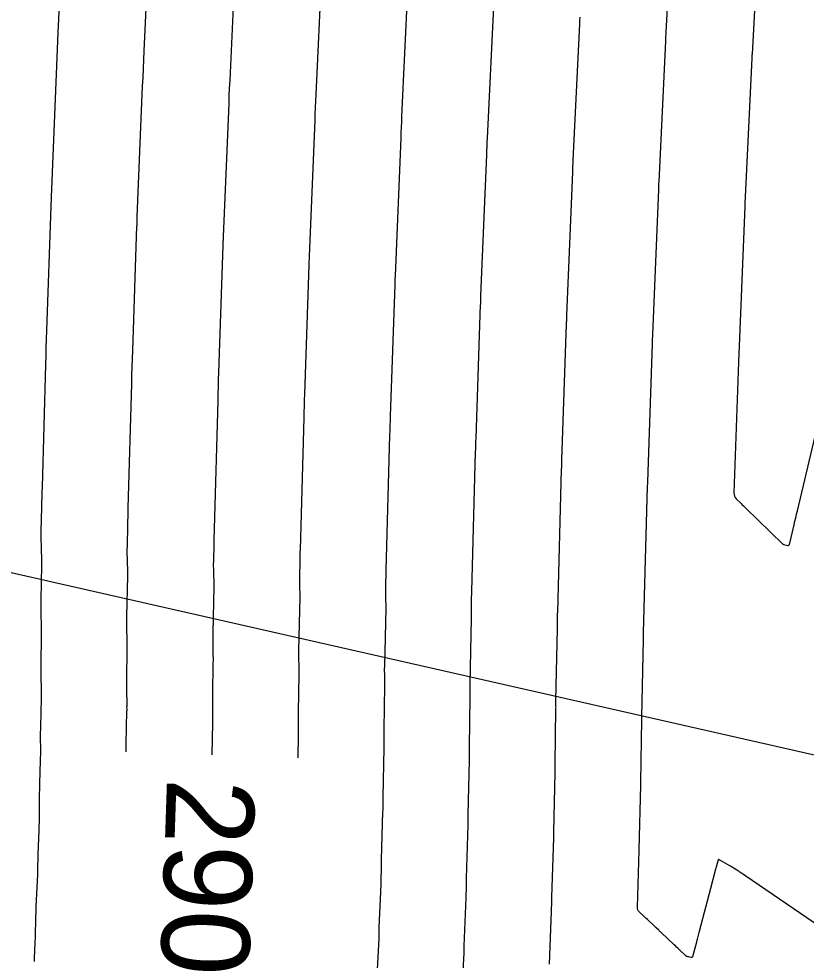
# Model space of a CAD drawing. Extents: x 1710723 to 1713003, y 548603 to 551142.
# Drawn here: x 1712182.6 to 1712236.2, y 549615.6 to 549679.7 of the extents above; entities that cross this region are included whole.
import ezdxf

# ---------------------------------------------------------------- set-up
doc = ezdxf.new("R2010")
doc.units = 0
for name, color, linetype in [('R_Contour Annot', 7, 'Continuous'), ('R_Contours', 7, 'Continuous'), ('R_Horz Alg', 7, 'Continuous'), ('R_Horz Alg Annot', 7, 'Continuous')]:
    doc.layers.add(name, color=color, linetype=linetype)

msp = doc.modelspace()

# ---------------------------------------------------------------- linework, layer by layer
at = {"layer": 'R_Contours'}
for points in [[(1712237.192, 549617.833), (1712232.116, 549621.311), (1712232.014, 549621.381), (1712231.912, 549621.451), (1712231.707, 549621.591), (1712231.656, 549621.626), (1712231.604, 549621.661), (1712231.552, 549621.694), (1712231.5, 549621.728), (1712231.251, 549621.885), (1712231.192, 549621.922), (1712231.132, 549621.959), (1712231.072, 549621.994), (1712231.012, 549622.028), (1712230.377, 549622.385), (1712230.347, 549622.402), (1712230.317, 549622.419), (1712230.257, 549622.452), (1712230.244, 549622.457), (1712230.233, 549622.456), (1712230.224, 549622.449), (1712230.219, 549622.435), (1712230.088, 549621.918), (1712230.08, 549621.888), (1712230.072, 549621.858), (1712230.065, 549621.828), (1712230.057, 549621.798), (1712229.706, 549620.462), (1712228.94, 549617.547), (1712228.93, 549617.511), (1712228.92, 549617.475), (1712228.798, 549617.017), (1712228.784, 549616.965), (1712228.77, 549616.913), (1712228.756, 549616.861), (1712228.742, 549616.809), (1712228.473, 549615.825), (1712228.46, 549615.796), (1712228.441, 549615.777), (1712228.416, 549615.77), (1712228.384, 549615.773), (1712228.207, 549615.819), (1712228.175, 549615.827), (1712228.144, 549615.835), (1712228.082, 549615.851), (1712228.067, 549615.856), (1712228.053, 549615.863), (1712228.04, 549615.872), (1712228.027, 549615.882), (1712227.562, 549616.327), (1712227.481, 549616.405), (1712227.399, 549616.483), (1712227.317, 549616.56), (1712227.235, 549616.638), (1712226.343, 549617.477), (1712226.301, 549617.516), (1712226.259, 549617.555), (1712226.217, 549617.595), (1712226.176, 549617.634), (1712226.009, 549617.792), (1712225.967, 549617.831), (1712225.926, 549617.87), (1712225.884, 549617.909), (1712225.842, 549617.949), (1712225.48, 549618.288), (1712225.406, 549618.357), (1712225.331, 549618.427), (1712225.257, 549618.496), (1712225.183, 549618.566), (1712224.877, 549618.852), (1712224.811, 549618.926), (1712224.765, 549619.01), (1712224.739, 549619.101), (1712224.732, 549619.2), (1712224.851, 549623.058), (1712224.851, 549623.074), (1712224.851, 549623.097), (1712224.851, 549623.105), (1712224.951, 549627.52), (1712224.951, 549627.536), (1712224.953, 549627.622), (1712224.953, 549627.641), (1712224.953, 549627.66), (1712224.953, 549627.699), (1712224.953, 549627.718), (1712224.953, 549627.738), (1712225.023, 549631.965), (1712225.023, 549631.979), (1712225.023, 549631.993), (1712225.023, 549632.008), (1712225.023, 549632.022), (1712225.022, 549632.079), (1712225.022, 549632.094), (1712225.021, 549632.108), (1712225.022, 549632.122), (1712225.022, 549632.136), (1712225.144, 549637.427), (1712225.144, 549637.433), (1712225.141, 549637.548), (1712225.14, 549637.567), (1712225.14, 549637.586), (1712225.14, 549637.605), (1712225.14, 549637.625), (1712225.144, 549637.764), (1712225.144, 549637.793), (1712225.145, 549637.823), (1712225.146, 549637.852), (1712225.147, 549637.882), (1712225.423, 549647.854), (1712225.425, 549647.933), (1712225.428, 549648.013), (1712225.43, 549648.093), (1712225.433, 549648.173), (1712225.754, 549657.576), (1712225.756, 549657.633), (1712225.758, 549657.69), (1712225.76, 549657.747), (1712225.762, 549657.804), (1712225.776, 549658.183), (1712225.777, 549658.199), (1712226.181, 549668.093), (1712226.186, 549668.221), (1712226.192, 549668.349), (1712226.198, 549668.476), (1712226.204, 549668.604), (1712226.659, 549678.194), (1712226.666, 549678.344), (1712226.673, 549678.494), (1712226.681, 549678.644), (1712226.689, 549678.794), (1712227.202, 549688.283)], [(1712233.062, 549687.11), (1712232.532, 549677.308), (1712232.528, 549677.237), (1712232.525, 549677.165), (1712232.521, 549677.094), (1712232.518, 549677.023), (1712232.048, 549667.117), (1712232.045, 549667.068), (1712232.043, 549667.02), (1712232.041, 549666.972), (1712232.039, 549666.923), (1712231.628, 549656.862), (1712231.628, 549656.848), (1712231.611, 549656.405), (1712231.609, 549656.361), (1712231.608, 549656.318), (1712231.304, 549647.413), (1712231.311, 549647.302), (1712231.339, 549647.2), (1712231.389, 549647.106), (1712231.46, 549647.02), (1712231.786, 549646.695), (1712231.868, 549646.614), (1712231.95, 549646.533), (1712232.033, 549646.452), (1712232.115, 549646.372), (1712234.642, 549643.932), (1712234.65, 549643.925), (1712234.658, 549643.92), (1712234.667, 549643.916), (1712234.676, 549643.913), (1712234.981, 549643.844), (1712235.018, 549643.841), (1712235.047, 549643.85), (1712235.069, 549643.872), (1712235.082, 549643.907), (1712235.403, 549645.248), (1712235.459, 549645.485), (1712235.516, 549645.722), (1712235.572, 549645.96), (1712235.629, 549646.197), (1712236.84, 549651.28)], [(1712183.664, 549615.5), (1712183.669, 549615.597), (1712183.673, 549615.694), (1712183.676, 549615.791), (1712183.687, 549616.188), (1712183.69, 549616.281), (1712183.694, 549616.374), (1712183.698, 549616.467), (1712183.703, 549616.56), (1712183.723, 549616.932), (1712183.728, 549617.026), (1712183.732, 549617.119), (1712183.735, 549617.212), (1712183.737, 549617.305), (1712183.761, 549618.391), (1712183.767, 549618.603), (1712183.773, 549618.815), (1712183.782, 549619.026), (1712183.791, 549619.238), (1712183.875, 549620.979), (1712183.882, 549621.129), (1712183.887, 549621.28), (1712183.891, 549621.43), (1712183.894, 549621.581), (1712183.903, 549622.184), (1712183.905, 549622.334), (1712183.909, 549622.485), (1712183.914, 549622.635), (1712183.919, 549622.786), (1712183.986, 549624.45), (1712183.989, 549624.516), (1712183.99, 549624.581), (1712183.992, 549624.646), (1712183.993, 549624.711), (1712183.996, 549625.02), (1712183.996, 549625.061), (1712183.997, 549625.103), (1712183.998, 549625.144), (1712184, 549625.186), (1712184.006, 549625.352), (1712184.007, 549625.393), (1712184.008, 549625.435), (1712184.009, 549625.476), (1712184.009, 549625.518), (1712184.014, 549626.747), (1712184.016, 549626.966), (1712184.019, 549627.185), (1712184.023, 549627.404), (1712184.029, 549627.622), (1712184.078, 549629.201), (1712184.083, 549629.392), (1712184.087, 549629.583), (1712184.088, 549629.775), (1712184.088, 549629.966), (1712184.085, 549630.732), (1712184.085, 549630.923), (1712184.086, 549631.115), (1712184.088, 549631.306), (1712184.092, 549631.497), (1712184.136, 549633.416), (1712184.136, 549633.447), (1712184.137, 549633.478), (1712184.137, 549633.509), (1712184.136, 549633.54), (1712184.135, 549633.711), (1712184.135, 549633.725), (1712184.135, 549633.739), (1712184.136, 549633.775), (1712184.136, 549633.79), (1712184.136, 549633.797), (1712184.117, 549635.134), (1712184.115, 549635.36), (1712184.114, 549635.585), (1712184.116, 549635.81), (1712184.118, 549636.036), (1712184.141, 549637.402), (1712184.144, 549637.63), (1712184.144, 549637.859), (1712184.143, 549638.087), (1712184.139, 549638.315), (1712184.118, 549639.229), (1712184.114, 549639.457), (1712184.113, 549639.686), (1712184.114, 549639.914), (1712184.118, 549640.142), (1712184.173, 549642.493), (1712184.173, 549642.505), (1712184.173, 549642.516), (1712184.171, 549642.561), (1712184.133, 549643.904), (1712184.128, 549644.13), (1712184.126, 549644.356), (1712184.127, 549644.581), (1712184.131, 549644.807), (1712184.168, 549646.432), (1712184.176, 549646.778), (1712184.184, 549647.124), (1712184.193, 549647.47), (1712184.203, 549647.816), (1712184.434, 549656.158), (1712184.451, 549656.736), (1712184.468, 549657.314), (1712184.486, 549657.892), (1712184.506, 549658.47), (1712184.794, 549666.933), (1712184.796, 549666.991), (1712184.799, 549667.05), (1712184.813, 549667.424), (1712184.815, 549667.49), (1712184.818, 549667.555), (1712185.184, 549676.513), (1712185.207, 549677.081), (1712185.232, 549677.65), (1712185.258, 549678.218), (1712185.284, 549678.787), (1712185.659, 549686.693)], [(1712189.909, 549629.771), (1712189.909, 549629.805), (1712189.91, 549629.969), (1712189.912, 549630.134), (1712189.915, 549630.298), (1712189.966, 549632.574), (1712189.967, 549632.6), (1712189.967, 549632.627), (1712189.967, 549632.654), (1712189.967, 549632.68), (1712189.966, 549632.824), (1712189.966, 549632.84), (1712189.966, 549632.857), (1712189.967, 549632.889), (1712189.967, 549632.905), (1712189.967, 549632.921), (1712189.951, 549634.072), (1712189.949, 549634.267), (1712189.948, 549634.461), (1712189.949, 549634.656), (1712189.952, 549634.85), (1712189.981, 549636.625), (1712189.984, 549636.823), (1712189.984, 549637.021), (1712189.983, 549637.218), (1712189.979, 549637.416), (1712189.961, 549638.207), (1712189.958, 549638.405), (1712189.957, 549638.603), (1712189.958, 549638.801), (1712189.962, 549638.999), (1712190.026, 549641.77), (1712190.026, 549641.784), (1712190.025, 549641.829), (1712189.992, 549642.996), (1712189.987, 549643.192), (1712189.986, 549643.389), (1712189.986, 549643.585), (1712189.989, 549643.781), (1712190.021, 549645.194), (1712190.028, 549645.494), (1712190.036, 549645.795), (1712190.044, 549646.096), (1712190.052, 549646.397), (1712190.286, 549654.854), (1712190.302, 549655.42), (1712190.32, 549655.986), (1712190.337, 549656.551), (1712190.356, 549657.117), (1712190.646, 549665.596), (1712190.648, 549665.663), (1712190.65, 549665.729), (1712190.664, 549666.103), (1712190.667, 549666.161), (1712190.669, 549666.219), (1712191.032, 549675.115), (1712191.058, 549675.718), (1712191.084, 549676.321), (1712191.111, 549676.924), (1712191.139, 549677.527), (1712191.504, 549685.224)], [(1712197.363, 549684.053), (1712196.983, 549676.04), (1712196.959, 549675.516), (1712196.935, 549674.992), (1712196.912, 549674.469), (1712196.891, 549673.945), (1712196.52, 549664.882), (1712196.518, 549664.832), (1712196.516, 549664.782), (1712196.502, 549664.409), (1712196.501, 549664.371), (1712196.5, 549664.334), (1712196.498, 549664.297), (1712196.497, 549664.259), (1712196.202, 549655.626), (1712196.186, 549655.142), (1712196.171, 549654.657), (1712196.156, 549654.172), (1712196.142, 549653.687), (1712195.901, 549644.978), (1712195.894, 549644.722), (1712195.887, 549644.466), (1712195.881, 549644.211), (1712195.875, 549643.955), (1712195.848, 549642.755), (1712195.845, 549642.588), (1712195.845, 549642.422), (1712195.846, 549642.255), (1712195.85, 549642.088), (1712195.878, 549641.096), (1712195.879, 549641.058), (1712195.879, 549641.046), (1712195.805, 549637.855), (1712195.802, 549637.688), (1712195.801, 549637.52), (1712195.802, 549637.353), (1712195.805, 549637.186), (1712195.82, 549636.517), (1712195.823, 549636.35), (1712195.824, 549636.183), (1712195.824, 549636.016), (1712195.822, 549635.848), (1712195.785, 549633.665), (1712195.783, 549633.501), (1712195.782, 549633.337), (1712195.783, 549633.174), (1712195.784, 549633.01), (1712195.798, 549632.046), (1712195.798, 549632.028), (1712195.798, 549632.01), (1712195.797, 549631.974), (1712195.797, 549631.956), (1712195.797, 549631.938), (1712195.798, 549631.821), (1712195.798, 549631.799), (1712195.798, 549631.776), (1712195.798, 549631.754), (1712195.797, 549631.732), (1712195.748, 549629.577)], [(1712203.222, 549682.881), (1712202.827, 549674.553), (1712202.806, 549674.108), (1712202.786, 549673.664), (1712202.767, 549673.219), (1712202.749, 549672.774), (1712202.372, 549663.545), (1712202.37, 549663.503), (1712202.368, 549663.461), (1712202.354, 549663.088), (1712202.353, 549663.046), (1712202.351, 549663.005), (1712202.35, 549662.964), (1712202.348, 549662.923), (1712202.049, 549654.135), (1712202.035, 549653.732), (1712202.022, 549653.328), (1712202.01, 549652.924), (1712201.999, 549652.521), (1712201.75, 549643.558), (1712201.744, 549643.348), (1712201.739, 549643.138), (1712201.734, 549642.927), (1712201.729, 549642.717), (1712201.706, 549641.729), (1712201.704, 549641.592), (1712201.704, 549641.454), (1712201.705, 549641.317), (1712201.708, 549641.18), (1712201.731, 549640.36), (1712201.732, 549640.332), (1712201.732, 549640.322), (1712201.648, 549636.711), (1712201.646, 549636.575), (1712201.645, 549636.438), (1712201.646, 549636.301), (1712201.648, 549636.165), (1712201.66, 549635.618), (1712201.663, 549635.482), (1712201.664, 549635.345), (1712201.664, 549635.208), (1712201.662, 549635.072), (1712201.619, 549632.479), (1712201.617, 549632.346), (1712201.616, 549632.214), (1712201.617, 549632.081), (1712201.618, 549631.948), (1712201.629, 549631.17), (1712201.629, 549631.15), (1712201.629, 549631.131), (1712201.628, 549631.091), (1712201.628, 549631.071), (1712201.628, 549631.052), (1712201.629, 549630.962), (1712201.629, 549630.944), (1712201.629, 549630.926), (1712201.628, 549630.908), (1712201.628, 549630.889), (1712201.594, 549629.382)], [(1712209.081, 549681.709), (1712208.671, 549673.066), (1712208.654, 549672.7), (1712208.638, 549672.335), (1712208.622, 549671.97), (1712208.607, 549671.604), (1712208.223, 549662.209), (1712208.221, 549662.158), (1712208.215, 549662.004), (1712208.206, 549661.767), (1712208.205, 549661.722), (1712208.203, 549661.676), (1712208.201, 549661.631), (1712208.2, 549661.586), (1712207.895, 549652.645), (1712207.884, 549652.322), (1712207.874, 549651.999), (1712207.864, 549651.677), (1712207.855, 549651.354), (1712207.599, 549642.139), (1712207.595, 549641.974), (1712207.59, 549641.809), (1712207.586, 549641.644), (1712207.582, 549641.479), (1712207.565, 549640.703), (1712207.563, 549640.595), (1712207.563, 549640.487), (1712207.564, 549640.38), (1712207.566, 549640.272), (1712207.584, 549639.628), (1712207.585, 549639.606), (1712207.585, 549639.598), (1712207.492, 549635.568), (1712207.49, 549635.461), (1712207.489, 549635.355), (1712207.49, 549635.249), (1712207.492, 549635.143), (1712207.501, 549634.719), (1712207.503, 549634.613), (1712207.504, 549634.507), (1712207.504, 549634.401), (1712207.502, 549634.295), (1712207.452, 549631.294), (1712207.451, 549631.192), (1712207.45, 549631.09), (1712207.451, 549630.988), (1712207.452, 549630.886), (1712207.46, 549630.295), (1712207.46, 549630.273), (1712207.46, 549630.252), (1712207.459, 549630.208), (1712207.459, 549630.187), (1712207.459, 549630.165), (1712207.459, 549630.103), (1712207.459, 549630.089), (1712207.459, 549630.075), (1712207.459, 549630.061), (1712207.459, 549630.047), (1712207.383, 549626.702), (1712207.381, 549626.617), (1712207.38, 549626.533), (1712207.38, 549626.449), (1712207.38, 549626.365), (1712207.381, 549626.028), (1712207.381, 549625.943), (1712207.381, 549625.859), (1712207.379, 549625.775), (1712207.377, 549625.69), (1712207.277, 549622.459), (1712207.275, 549622.366), (1712207.273, 549622.272), (1712207.271, 549622.179), (1712207.271, 549622.085), (1712207.269, 549621.648), (1712207.268, 549621.586), (1712207.267, 549621.524), (1712207.266, 549621.463), (1712207.264, 549621.401), (1712207.253, 549621.085), (1712207.252, 549621.057), (1712207.251, 549621.029), (1712207.25, 549621.001), (1712207.25, 549620.974), (1712207.249, 549620.863), (1712207.248, 549620.835), (1712207.248, 549620.807), (1712207.247, 549620.779), (1712207.246, 549620.752), (1712207.128, 549617.807), (1712207.125, 549617.745), (1712207.123, 549617.683), (1712207.122, 549617.62), (1712207.121, 549617.558), (1712207.117, 549617.309), (1712207.116, 549617.246), (1712207.114, 549617.184), (1712207.112, 549617.122), (1712207.109, 549617.059), (1712206.947, 549613.685)], [(1712212.735, 549612.297), (1712212.918, 549616.08), (1712212.92, 549616.12), (1712212.921, 549616.16), (1712212.922, 549616.2), (1712212.923, 549616.241), (1712212.925, 549616.402), (1712212.926, 549616.442), (1712212.927, 549616.482), (1712212.928, 549616.522), (1712212.93, 549616.563), (1712213.061, 549619.827), (1712213.062, 549619.845), (1712213.062, 549619.864), (1712213.063, 549619.882), (1712213.063, 549619.9), (1712213.064, 549619.974), (1712213.064, 549619.992), (1712213.064, 549620.011), (1712213.065, 549620.029), (1712213.065, 549620.047), (1712213.079, 549620.423), (1712213.081, 549620.485), (1712213.082, 549620.547), (1712213.083, 549620.609), (1712213.084, 549620.671), (1712213.085, 549620.92), (1712213.085, 549620.982), (1712213.086, 549621.044), (1712213.087, 549621.107), (1712213.089, 549621.169), (1712213.202, 549624.813), (1712213.203, 549624.87), (1712213.204, 549624.928), (1712213.205, 549624.985), (1712213.205, 549625.043), (1712213.204, 549625.273), (1712213.204, 549625.33), (1712213.204, 549625.388), (1712213.205, 549625.445), (1712213.206, 549625.503), (1712213.29, 549629.205), (1712213.29, 549629.224), (1712213.29, 549629.244), (1712213.29, 549629.283), (1712213.29, 549629.302), (1712213.29, 549629.322), (1712213.291, 549629.372), (1712213.291, 549629.384), (1712213.291, 549629.396), (1712213.291, 549629.407), (1712213.291, 549629.419), (1712213.285, 549629.823), (1712213.285, 549629.895), (1712213.285, 549629.966), (1712213.285, 549630.037), (1712213.286, 549630.108), (1712213.343, 549633.518), (1712213.344, 549633.594), (1712213.344, 549633.669), (1712213.343, 549633.745), (1712213.342, 549633.82), (1712213.335, 549634.122), (1712213.334, 549634.197), (1712213.333, 549634.273), (1712213.334, 549634.348), (1712213.335, 549634.424), (1712213.438, 549638.874), (1712213.438, 549638.882), (1712213.437, 549638.898), (1712213.424, 549639.364), (1712213.423, 549639.442), (1712213.422, 549639.52), (1712213.422, 549639.599), (1712213.423, 549639.677), (1712213.436, 549640.24), (1712213.439, 549640.36), (1712213.442, 549640.48), (1712213.445, 549640.6), (1712213.448, 549640.72), (1712213.711, 549650.187), (1712213.718, 549650.429), (1712213.725, 549650.671), (1712213.733, 549650.912), (1712213.741, 549651.154), (1712214.051, 549660.249), (1712214.053, 549660.299), (1712214.055, 549660.348), (1712214.056, 549660.397), (1712214.058, 549660.446), (1712214.072, 549660.82), (1712214.074, 549660.872), (1712214.465, 549670.434), (1712214.477, 549670.72), (1712214.489, 549671.006), (1712214.502, 549671.292), (1712214.515, 549671.578), (1712214.94, 549680.538)], [(1712218.732, 549615.318), (1712218.876, 549618.902), (1712218.877, 549618.92), (1712218.877, 549618.938), (1712218.877, 549618.974), (1712218.878, 549618.992), (1712218.878, 549619.01), (1712218.896, 549619.508), (1712218.897, 549619.538), (1712218.898, 549619.569), (1712218.898, 549619.6), (1712218.898, 549619.631), (1712218.899, 549619.754), (1712218.899, 549619.785), (1712218.9, 549619.816), (1712218.9, 549619.847), (1712218.901, 549619.878), (1712219.026, 549623.935), (1712219.027, 549623.966), (1712219.028, 549623.997), (1712219.028, 549624.027), (1712219.028, 549624.058), (1712219.027, 549624.181), (1712219.027, 549624.212), (1712219.028, 549624.243), (1712219.028, 549624.273), (1712219.029, 549624.304), (1712219.121, 549628.363), (1712219.121, 549628.379), (1712219.121, 549628.412), (1712219.121, 549628.429), (1712219.122, 549628.493), (1712219.122, 549628.506), (1712219.122, 549628.518), (1712219.122, 549628.531), (1712219.122, 549628.544), (1712219.119, 549628.761), (1712219.119, 549628.802), (1712219.119, 549628.842), (1712219.119, 549628.883), (1712219.119, 549628.923), (1712219.183, 549632.741), (1712219.183, 549632.786), (1712219.184, 549632.831), (1712219.183, 549632.876), (1712219.182, 549632.921), (1712219.178, 549633.101), (1712219.178, 549633.145), (1712219.177, 549633.19), (1712219.178, 549633.235), (1712219.178, 549633.28), (1712219.291, 549638.151), (1712219.291, 549638.165), (1712219.282, 549638.456), (1712219.281, 549638.504), (1712219.281, 549638.553), (1712219.281, 549638.602), (1712219.282, 549638.651), (1712219.29, 549639.002), (1712219.292, 549639.077), (1712219.293, 549639.151), (1712219.295, 549639.226), (1712219.297, 549639.301), (1712219.567, 549649.02), (1712219.572, 549649.181), (1712219.576, 549649.342), (1712219.582, 549649.503), (1712219.587, 549649.663), (1712219.903, 549658.913), (1712219.904, 549658.966), (1712219.906, 549659.019), (1712219.908, 549659.072), (1712219.91, 549659.125), (1712219.924, 549659.499), (1712219.926, 549659.535), (1712220.323, 549669.264), (1712220.332, 549669.471), (1712220.341, 549669.677), (1712220.35, 549669.884), (1712220.36, 549670.091), (1712220.8, 549679.366), (1712220.811, 549679.594), (1712220.822, 549679.823)]]:
    msp.add_lwpolyline(points, dxfattribs=at)
at = {"layer": 'R_Horz Alg'}
msp.add_arc((1711727.021, 549745.305), 532.984, 270.64281, 347.20664, dxfattribs=at)
at = {"layer": 'R_Horz Alg Annot'}
msp.add_lwpolyline([(1712246.774, 549627.283), (1712129.753, 549653.855)], dxfattribs=at)

# ---------------------------------------------------------------- texts
at = {"layer": 'R_Contour Annot'}
msp.add_text('290', height=6, rotation=268.09604, dxfattribs=at).set_placement((1712192.695, 549628.024))

doc.saveas('drawing.dxf')
